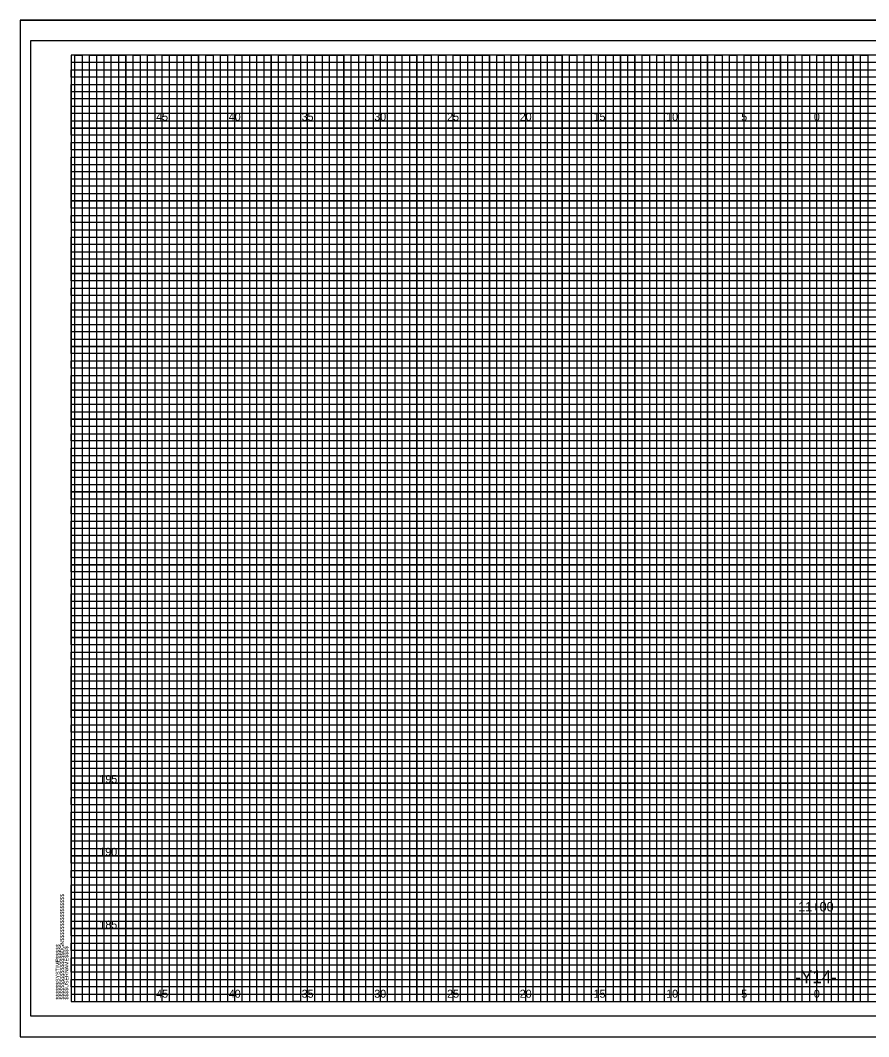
# Model space of a CAD drawing. Extents: x -4 to 103, y -2 to 138.
# Drawn here: x -3.5 to 54.8, y 68.4 to 138.2 of the extents above; entities that cross this region are included whole.
import ezdxf

# ---------------------------------------------------------------- set-up
doc = ezdxf.new("R2010")
doc.units = 0
for name, color, linetype in [('Old_Level_10', 7, 'Continuous'), ('Old_Level_16', 7, 'Continuous'), ('Old_Level_3', 7, 'Continuous'), ('Old_Level_5', 7, 'Continuous'), ('Old_Level_8', 7, 'Continuous'), ('Prop Dimension', 7, 'Continuous'), ('Prop XS Finish Grade Earthwork', 7, 'Continuous'), ('Prop XS Pvmt Edge Slope', 7, 'Continuous'), ('Prop XS SE Text', 7, 'Continuous'), ('Prop XS Subgrade Earthwork', 7, 'Continuous'), ('Prop XSC Text', 7, 'Continuous')]:
    doc.layers.add(name, color=color, linetype=linetype)

msp = doc.modelspace()

# ---------------------------------------------------------------- linework, layer by layer
at = {"layer": 'Old_Level_10'}
for p, q in [((1.25, 70.825), (1.25, 135.825)), ((3.75, 70.825), (3.75, 135.825)), ((6.25, 70.825), (6.25, 135.825)), ((8.75, 70.825), (8.75, 135.825)), ((11.25, 70.825), (11.25, 135.825)), ((13.75, 70.825), (13.75, 135.825)), ((16.25, 70.825), (16.25, 135.825)), ((18.75, 70.825), (18.75, 135.825)), ((21.25, 70.825), (21.25, 135.825)), ((23.75, 70.825), (23.75, 135.825)), ((26.25, 70.825), (26.25, 135.825)), ((28.75, 70.825), (28.75, 135.825)), ((31.25, 70.825), (31.25, 135.825)), ((33.75, 70.825), (33.75, 135.825)), ((36.25, 70.825), (36.25, 135.825)), ((38.75, 70.825), (38.75, 135.825)), ((41.25, 70.825), (41.25, 135.825)), ((43.75, 70.825), (43.75, 135.825)), ((46.25, 70.825), (46.25, 135.825)), ((48.75, 70.825), (48.75, 135.825)), ((51.25, 70.825), (51.25, 135.825)), ((53.75, 70.825), (53.75, 135.825)), ((0, 133.325), (74.25, 133.325)), ((0, 130.825), (102.5, 130.825)), ((0, 128.325), (102.5, 128.325)), ((0, 125.825), (102.5, 125.825)), ((0, 123.325), (102.5, 123.325)), ((0, 120.825), (102.5, 120.825)), ((0, 118.325), (102.5, 118.325)), ((0, 115.825), (102.5, 115.825)), ((0, 113.325), (102.5, 113.325)), ((0, 110.825), (102.5, 110.825)), ((0, 108.325), (102.5, 108.325)), ((0, 105.825), (102.5, 105.825)), ((0, 103.325), (102.5, 103.325)), ((0, 100.825), (102.5, 100.825)), ((0, 98.325), (102.5, 98.325)), ((0, 95.825), (102.5, 95.825)), ((0, 93.325), (102.5, 93.325)), ((0, 90.825), (102.5, 90.825)), ((0, 88.325), (102.5, 88.325)), ((0, 85.825), (102.5, 85.825)), ((0, 83.325), (102.5, 83.325)), ((0, 80.825), (102.5, 80.825)), ((0, 78.325), (102.5, 78.325)), ((0, 75.825), (102.5, 75.825)), ((0, 73.325), (102.5, 73.325))]:
    msp.add_line(p, q, dxfattribs=at)
at = {"layer": 'Old_Level_3'}
for p, q in [((-3.5, 138.225), (103.4, 138.225)), ((-3.5, 138.225), (-3.5, 68.4)), ((-3.5, 68.4), (103.4, 68.4))]:
    msp.add_line(p, q, dxfattribs=at)
at = {"layer": 'Old_Level_5'}
msp.add_lwpolyline([(103.4, 138.225), (-3.5, 138.225), (-3.5, 68.4), (103.4, 68.4)], close=True, dxfattribs=at)
at = {"layer": 'Old_Level_8'}
for points in [[(1.25, 70.825), (1.25, 135.825), (3.75, 135.825), (3.75, 70.825), (6.25, 70.825), (6.25, 135.825), (8.75, 135.825), (8.75, 70.825), (11.25, 70.825), (11.25, 135.825), (13.75, 135.825), (13.75, 70.825), (16.25, 70.825), (16.25, 135.825), (18.75, 135.825), (18.75, 70.825), (21.25, 70.825), (21.25, 135.825), (23.75, 135.825), (23.75, 70.825), (26.25, 70.825), (26.25, 135.825), (28.75, 135.825), (28.75, 70.825), (31.25, 70.825), (31.25, 135.825), (33.75, 135.825), (33.75, 70.825), (36.25, 70.825), (36.25, 135.825), (38.75, 135.825), (38.75, 70.825), (41.25, 70.825), (41.25, 135.825), (43.75, 135.825), (43.75, 70.825), (46.25, 70.825), (46.25, 135.825), (48.75, 135.825), (48.75, 70.825), (51.25, 70.825), (51.25, 135.825), (53.75, 135.825), (53.75, 70.825)], [(102.5, 130.825), (0, 130.825), (0, 133.325), (74.25, 133.325)], [(102.5, 125.825), (0, 125.825), (0, 128.325), (102.5, 128.325)], [(102.5, 120.825), (0, 120.825), (0, 123.325), (102.5, 123.325)], [(102.5, 115.825), (0, 115.825), (0, 118.325), (102.5, 118.325)], [(102.5, 110.825), (0, 110.825), (0, 113.325), (102.5, 113.325)], [(102.5, 105.825), (0, 105.825), (0, 108.325), (102.5, 108.325)], [(102.5, 100.825), (0, 100.825), (0, 103.325), (102.5, 103.325)], [(102.5, 95.825), (0, 95.825), (0, 98.325), (102.5, 98.325)], [(102.5, 90.825), (0, 90.825), (0, 93.325), (102.5, 93.325)], [(102.5, 85.825), (0, 85.825), (0, 88.325), (102.5, 88.325)], [(102.5, 80.825), (0, 80.825), (0, 83.325), (102.5, 83.325)], [(102.5, 75.825), (0, 75.825), (0, 78.325), (102.5, 78.325)], [(0, 73.325), (102.5, 73.325)]]:
    msp.add_lwpolyline(points, dxfattribs=at)
at = {"layer": 'Prop Dimension'}
for points in [[(0.25, 70.825), (0.25, 135.825), (0.75, 135.825), (0.75, 70.825), (1.75, 70.825), (1.75, 135.825), (2.25, 135.825), (2.25, 70.825), (2.75, 70.825), (2.75, 135.825), (3.25, 135.825), (3.25, 70.825), (4.25, 70.825), (4.25, 135.825), (4.75, 135.825), (4.75, 70.825), (5.25, 70.825), (5.25, 135.825), (5.75, 135.825), (5.75, 70.825), (6.75, 70.825), (6.75, 135.825), (7.25, 135.825), (7.25, 70.825), (7.75, 70.825), (7.75, 135.825), (8.25, 135.825), (8.25, 70.825), (9.25, 70.825), (9.25, 135.825), (9.75, 135.825), (9.75, 70.825), (10.25, 70.825), (10.25, 135.825), (10.75, 135.825), (10.75, 70.825), (11.75, 70.825), (11.75, 135.825), (12.25, 135.825), (12.25, 70.825), (12.75, 70.825), (12.75, 135.825), (13.25, 135.825), (13.25, 70.825), (14.25, 70.825), (14.25, 135.825), (14.75, 135.825), (14.75, 70.825), (15.75, 70.825), (15.25, 70.825), (15.25, 135.825), (15.75, 135.825), (15.75, 70.825), (16.75, 70.825), (16.75, 135.825), (17.25, 135.825), (17.25, 70.825), (17.75, 70.825), (17.75, 135.825), (18.25, 135.825), (18.25, 70.825), (19.25, 70.825), (19.25, 135.825), (19.75, 135.825), (19.75, 70.825), (20.25, 70.825), (20.25, 135.825), (20.75, 135.825), (20.75, 70.825), (21.75, 70.825), (21.75, 135.825), (22.25, 135.825), (22.25, 70.825), (22.75, 70.825), (22.75, 135.825), (23.25, 135.825), (23.25, 70.825), (24.25, 70.825), (24.25, 135.825), (24.75, 135.825), (24.75, 70.825), (25.25, 70.825), (25.25, 135.825), (25.75, 135.825), (25.75, 70.825), (26.75, 70.825), (26.75, 135.825), (27.25, 135.825), (27.25, 70.825), (27.75, 70.825), (27.75, 135.825), (28.25, 135.825), (28.25, 70.825), (29.25, 70.825), (29.25, 135.825), (29.75, 135.825), (29.75, 70.825), (30.25, 70.825), (30.25, 135.825), (30.75, 135.825), (30.75, 70.825)], [(30.75, 70.825), (31.75, 70.825), (31.75, 135.825), (32.25, 135.825), (32.25, 70.825), (32.75, 70.825), (32.75, 135.825), (33.25, 135.825), (33.25, 70.825), (34.25, 70.825), (34.25, 135.825), (34.75, 135.825), (34.75, 70.825), (35.25, 70.825), (35.25, 135.825), (35.75, 135.825), (35.75, 70.825), (36.75, 70.825), (36.75, 135.825), (37.25, 135.825), (37.25, 70.825), (37.75, 70.825), (37.75, 135.825), (37.75, 70.825)], [(38.25, 135.825), (38.25, 70.825), (39.25, 70.825), (39.25, 135.825), (39.75, 135.825), (39.75, 70.825), (40.25, 70.825), (40.25, 135.825), (40.75, 135.825), (40.75, 70.825), (41.75, 70.825), (41.75, 135.825), (42.25, 135.825), (42.25, 70.825), (42.75, 70.825), (42.75, 135.825), (43.25, 135.825), (43.25, 70.825), (43.75, 70.825), (44.25, 70.825), (44.25, 135.825), (44.75, 135.825), (44.75, 70.825), (45.25, 70.825), (45.25, 135.825), (45.75, 135.825), (45.75, 70.825), (46.75, 70.825), (46.75, 135.825), (47.25, 135.825), (47.25, 70.825), (47.75, 70.825), (47.75, 135.825), (48.25, 135.825), (48.25, 70.825), (49.25, 70.825), (49.25, 135.825), (49.75, 135.825), (49.75, 70.825), (50.25, 70.825), (50.25, 135.825), (50.75, 135.825), (50.75, 70.825), (51.75, 70.825), (51.75, 135.825), (52.25, 135.825), (52.25, 70.825), (52.75, 70.825), (52.75, 135.825), (53.25, 135.825), (53.25, 70.825), (54.25, 70.825), (54.25, 135.825), (54.75, 135.825), (54.75, 70.825), (55.25, 70.825)], [(0, 132.825), (0, 133.825), (74.25, 133.825), (74.25, 134.325), (0, 134.325), (0, 134.825), (74.25, 134.825), (74.25, 135.325), (0, 135.325)], [(102.5, 132.825), (0, 132.825)], [(102.5, 131.825), (0, 131.825), (0, 132.325), (102.5, 132.325)], [(102.5, 130.325), (0, 130.325), (0, 131.325), (102.5, 131.325)], [(102.5, 129.325), (0, 129.325), (0, 129.825), (102.5, 129.825)], [(102.5, 127.825), (0, 127.825), (0, 128.825), (102.5, 128.825)], [(102.5, 126.825), (0, 126.825), (0, 127.325), (102.5, 127.325)], [(102.5, 125.325), (0, 125.325), (0, 126.325), (102.5, 126.325)], [(102.5, 124.325), (0, 124.325), (0, 124.825), (102.5, 124.825)], [(0, 123.825), (102.5, 123.825)], [(102.5, 122.825), (0, 122.825)], [(102.5, 121.825), (0, 121.825), (0, 122.325), (102.5, 122.325)], [(102.5, 120.325), (0, 120.325), (0, 121.325), (102.5, 121.325)], [(102.5, 119.325), (0, 119.325), (0, 119.825), (102.5, 119.825)], [(102.5, 117.825), (0, 117.825), (0, 118.825), (102.5, 118.825)], [(102.5, 116.825), (0, 116.825), (0, 117.325), (102.5, 117.325)], [(102.5, 115.325), (0, 115.325), (0, 116.325), (102.5, 116.325)], [(102.5, 114.325), (0, 114.325), (0, 114.825), (102.5, 114.825)], [(102.5, 112.825), (0, 112.825), (0, 113.825), (102.5, 113.825)], [(102.5, 111.825), (0, 111.825), (0, 112.325), (102.5, 112.325)], [(102.5, 110.325), (0, 110.325), (0, 111.325), (102.5, 111.325)], [(102.5, 109.325), (0, 109.325), (0, 109.825), (102.5, 109.825)], [(102.5, 107.825), (0, 107.825), (0, 108.825), (102.5, 108.825)], [(102.5, 106.825), (0, 106.825), (0, 107.325), (102.5, 107.325)], [(102.5, 105.325), (0, 105.325), (0, 106.325), (102.5, 106.325)], [(102.5, 104.325), (0, 104.325), (0, 104.825), (102.5, 104.825)], [(102.5, 102.825), (0, 102.825), (0, 103.825), (102.5, 103.825)], [(102.5, 101.825), (0, 101.825), (0, 102.325)], [(0, 102.325), (102.5, 102.325)], [(102.5, 100.325), (0, 100.325), (0, 101.325), (102.5, 101.325)], [(102.5, 99.325), (0, 99.325), (0, 99.825), (102.5, 99.825)], [(102.5, 97.825), (0, 97.825), (0, 98.825), (102.5, 98.825)], [(102.5, 96.825), (0, 96.825), (0, 97.325), (102.5, 97.325)], [(102.5, 95.325), (0, 95.325), (0, 96.325), (102.5, 96.325)], [(102.5, 94.325), (0, 94.325), (0, 94.825), (102.5, 94.825)], [(102.5, 92.825), (0, 92.825), (0, 93.825), (102.5, 93.825)], [(102.5, 91.825), (0, 91.825), (0, 92.325), (102.5, 92.325)], [(102.5, 90.325), (0, 90.325), (0, 91.325), (102.5, 91.325)], [(102.5, 89.325), (0, 89.325), (0, 89.825), (102.5, 89.825)], [(102.5, 87.825), (0, 87.825), (0, 88.825), (102.5, 88.825)], [(102.5, 86.825), (0, 86.825), (0, 87.325), (102.5, 87.325)], [(102.5, 85.325), (0, 85.325), (0, 86.325), (102.5, 86.325)], [(102.5, 84.325), (0, 84.325), (0, 84.825), (102.5, 84.825)], [(102.5, 82.825), (0, 82.825), (0, 83.825), (102.5, 83.825)], [(102.5, 81.825), (0, 81.825), (0, 82.325), (102.5, 82.325)], [(102.5, 80.325), (0, 80.325), (0, 81.325), (102.5, 81.325)], [(102.5, 79.325), (0, 79.325), (0, 79.825), (102.5, 79.825)], [(102.5, 77.825), (0, 77.825), (0, 78.825), (102.5, 78.825)], [(102.5, 76.825), (0, 76.825), (0, 77.325), (102.5, 77.325)], [(102.5, 75.325), (0, 75.325), (0, 76.325), (102.5, 76.325)], [(102.5, 74.325), (0, 74.325), (0, 74.825), (102.5, 74.825)], [(102.5, 72.825), (0, 72.825), (0, 73.825), (102.5, 73.825)], [(102.5, 71.825), (0, 71.825), (0, 72.325), (102.5, 72.325)], [(0, 71.325), (102.5, 71.325)]]:
    msp.add_lwpolyline(points, dxfattribs=at)
at = {"layer": 'Prop XS SE Text'}
msp.add_lwpolyline([(103, 136.825), (-2.8, 136.825), (-2.8, 69.825), (103, 69.825)], close=True, dxfattribs=at)
at = {"layer": 'Prop XSC Text'}
msp.add_lwpolyline([(102.5, 135.825), (0, 135.825), (0, 70.825), (102.5, 70.825)], close=True, dxfattribs=at)

# ---------------------------------------------------------------- texts
at = {"layer": 'Old_Level_16'}
for s, p in [('45', (5.84, 131.325)), ('40', (10.831, 131.325)), ('35', (15.84, 131.325)), ('30', (20.831, 131.325)), ('25', (25.84, 131.325)), ('20', (30.831, 131.325)), ('15', (35.906, 131.325)), ('10', (40.897, 131.325)), ('5', (46.057, 131.325)), ('0', (51.049, 131.325)), ('0', (51.049, 131.325)), ('45', (5.84, 71.075)), ('40', (10.831, 71.075)), ('35', (15.84, 71.075)), ('30', (20.831, 71.075)), ('25', (25.84, 71.075)), ('20', (30.831, 71.075)), ('15', (35.906, 71.075)), ('10', (40.897, 71.075)), ('5', (46.057, 71.075)), ('0', (51.049, 71.075)), ('0', (51.049, 71.075))]:
    msp.add_text(s, height=0.55, dxfattribs=at).set_placement(p)
at = {"layer": 'Old_Level_8'}
msp.add_text('040397', height=0.0025, rotation=90, dxfattribs=at).set_placement((-0.001, 135.811))
at = {"layer": 'Prop XS Finish Grade Earthwork'}
msp.add_text('-Y14-', height=0.875, dxfattribs=at).set_placement((49.773, 72.075))
at = {"layer": 'Prop XS Pvmt Edge Slope'}
msp.add_text('11+00', height=0.65, dxfattribs=at).set_placement((49.971, 77.006))
at = {"layer": 'Prop XS Subgrade Earthwork'}
for s, p in [('195', (1.938, 85.825)), ('190', (1.93, 80.825)), ('185', (1.938, 75.825))]:
    msp.add_text(s, height=0.55, dxfattribs=at).set_placement(p)
at = {"layer": 'Prop XSC Text'}
for s, p in [('$$$$$$$$$$$$$$$$DGN$$$$$$$$$$$$$$$$', (-0.5, 70.95)), ('$$$$$$SYSTIME$$$$$', (-0.797, 70.95)), ('$$$$USERNAME$$$$', (-0.2, 70.95))]:
    msp.add_text(s, height=0.2625, rotation=90, dxfattribs=at).set_placement(p)

doc.saveas('drawing.dxf')
